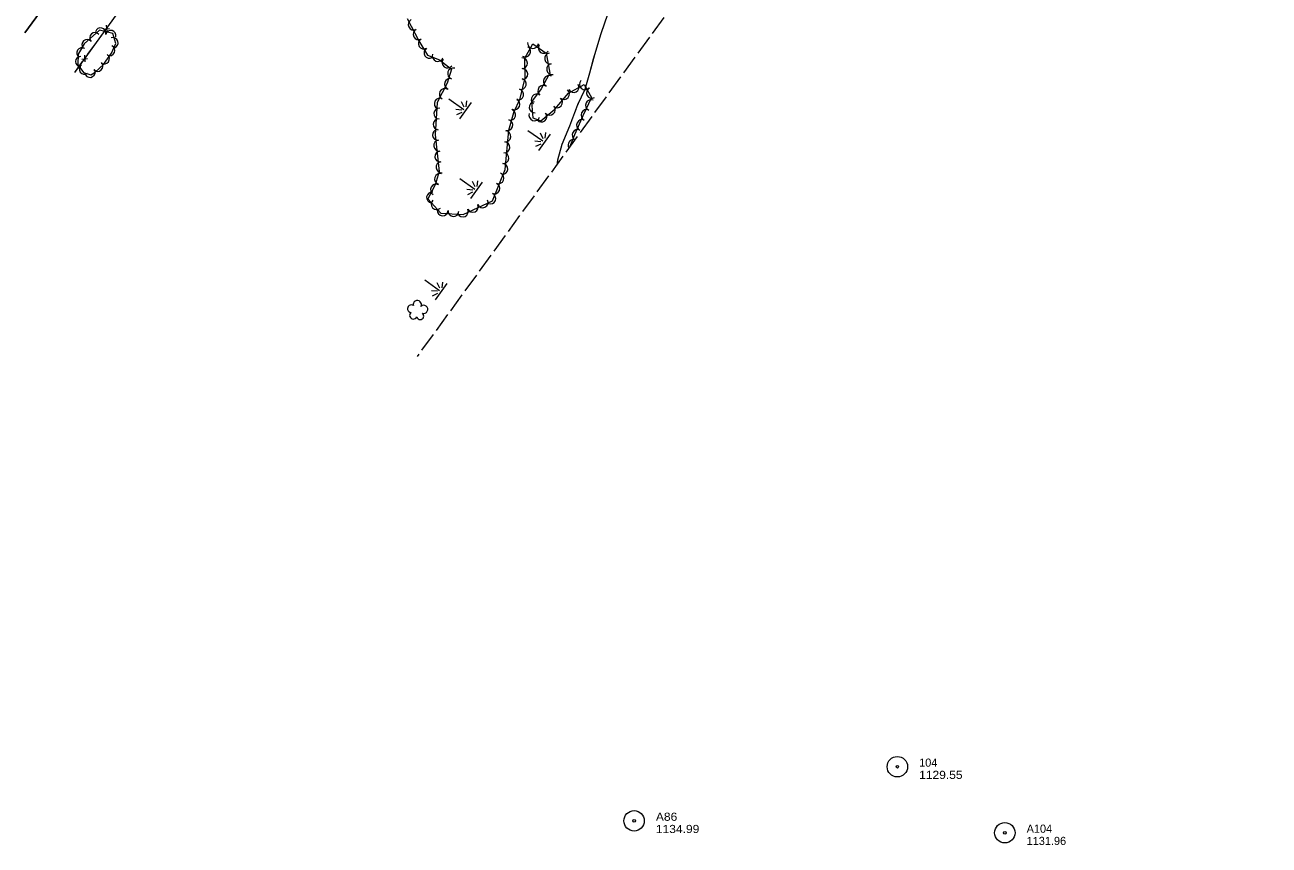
# Model space of a CAD drawing. Extents: x 297327 to 299792, y 46897 to 49095.
# Drawn here: x 298407 to 299321, y 46897 to 47500 of the extents above; entities that cross this region are included whole.
import ezdxf

# ---------------------------------------------------------------- set-up
doc = ezdxf.new("R2010")
doc.units = 0
doc.header["$LTSCALE"] = 2.4
doc.linetypes.add('LONG_DASHED', pattern=[7.5, 6, -1.5])
for name, color, linetype, lineweight in [('11', 7, 'Continuous', 25), ('15', 7, 'Continuous', 13), ('18', 7, 'Continuous', 13), ('19', 7, 'Continuous', 13), ('4', 7, 'Continuous', 13), ('6', 7, 'Continuous', 13)]:
    doc.layers.add(name, color=color, linetype=linetype, lineweight=lineweight)

msp = doc.modelspace()

# ---------------------------------------------------------------- linework, layer by layer
at = {"layer": '11'}
msp.add_lwpolyline([(298407.334, 47494.128), (298425.338, 47519.051)], dxfattribs=at)
at = {"layer": '15'}
for p, q in [((298467.752, 47494.906), (298467.331, 47499.713)), ((298459.972, 47487.112), (298465.708, 47494.99)), ((298465.288, 47496.907), (298469.407, 47497.292)), ((298453.451, 47478.155), (298459.972, 47487.112)), ((298443.923, 47465.07), (298449.659, 47472.948)), ((298449.238, 47474.864), (298453.358, 47475.25)), ((298451.703, 47472.864), (298451.282, 47477.671))]:
    msp.add_line(p, q, dxfattribs=at)
msp.add_lwpolyline([(298443.923, 47465.07), (298477.895, 47511.728), (298522.34, 47573.628), (298562.948, 47631.443), (298626.887, 47719.694), (298679.84, 47793.758), (298726.071, 47859.836), (298761.348, 47908.474)], dxfattribs=at)
at = {"layer": '18'}
for points in [[(298688.247, 47504.735), (298696.782, 47488.144), (298703.052, 47477.653), (298711.875, 47474.359), (298720.699, 47467.348), (298717.507, 47457.047), (298710.255, 47442.95), (298708.668, 47419.095), (298711.63, 47392.114), (298708.74, 47382.356), (298703.299, 47372.237), (298712.927, 47361.712), (298729.23, 47360.666), (298750.752, 47370.587), (298760.106, 47393.656), (298762.882, 47422.635), (298766.496, 47435.556), (298771.16, 47445.873), (298774.908, 47461.049), (298774.503, 47475.598), (298780.567, 47486.027), (298790.234, 47479.244), (298792.994, 47464.419), (298786.661, 47453.01), (298779.394, 47443.515), (298780.376, 47431.746), (298786.338, 47429.568), (298796.702, 47437.942), (298806.656, 47449.891), (298818.241, 47456.243), (298823.43, 47446.552), (298817.29, 47433.055)], [(298817.29, 47433.055), (298811.185, 47419.233), (298807.731, 47410.65)]]:
    msp.add_lwpolyline(points, dxfattribs=at)
msp.add_lwpolyline([(298465.043, 47470.761), (298470.86, 47479.099), (298474.225, 47486.323), (298471.894, 47493.739), (298462.226, 47496.177), (298450.977, 47486.121), (298446.39, 47478.389), (298446.333, 47470.596), (298450.458, 47464.98), (298455.86, 47463.292), (298458.863, 47465.109)], close=True, dxfattribs=at)
for centre, radius, start, end in [((298692.918, 47500.236), 4.004, 117.23056, 297.21524), ((298458.79, 47490.406), 3.845, 41.80266, 221.78734), ((298462.976, 47493.913), 3.845, 345.85435, 165.83902), ((298470.431, 47492.033), 3.845, 345.85435, 165.83902), ((298471.98, 47486.756), 3.845, 287.45666, 107.44134), ((298696.581, 47493.115), 4.004, 117.23056, 297.21524), ((298449.291, 47479.334), 3.845, 59.32918, 239.31385), ((298453.057, 47485.282), 3.845, 41.80266, 221.78734), ((298469.613, 47481.188), 3.845, 245.03116, 65.01584), ((298700.374, 47486.219), 4.004, 120.87253, 300.85721), ((298704.482, 47479.346), 4.004, 120.87253, 300.85721), ((298774.837, 47480.341), 4.004, 239.83156, 59.81624), ((298780.573, 47486.678), 4.004, 174.95165, 354.93633), ((298788.499, 47483.022), 4.004, 144.95165, 324.93633), ((298448.363, 47472.979), 3.845, 89.58859, 269.57327), ((298460.848, 47469.652), 3.845, 222.45255, 42.43723), ((298465.593, 47475.066), 3.845, 235.10613, 55.09081), ((298710.612, 47477.067), 4.004, 159.53492, 339.5196), ((298717.78, 47472.344), 4.004, 141.5392, 321.52387), ((298772.512, 47471.802), 4.004, 271.60219, 91.58687), ((298793.103, 47475.285), 4.004, 100.55379, 280.53847), ((298451.087, 47467.523), 3.845, 126.30526, 306.28994), ((298455.12, 47465.196), 3.845, 211.18418, 31.16886), ((298721.927, 47464.231), 4.004, 72.79087, 252.77555), ((298772.735, 47463.798), 4.004, 271.60219, 91.58687), ((298792.229, 47458.723), 4.004, 60.97353, 240.95821), ((298794.568, 47467.413), 4.004, 100.55379, 280.53847), ((298719.557, 47456.583), 4.004, 72.79087, 252.77555), ((298771.627, 47456.504), 4.004, 256.13499, 76.11967), ((298788.137, 47451.49), 4.004, 52.57902, 232.5637), ((298810.364, 47454.314), 4.004, 208.74341, 28.72809), ((298818.721, 47456.338), 4.004, 138.17427, 318.15895), ((298823.95, 47450.021), 4.004, 118.17427, 298.15895), ((298712.119, 47441.993), 4.004, 62.78476, 242.76943), ((298715.782, 47449.113), 4.004, 62.78476, 242.76943), ((298766.951, 47441.651), 4.004, 245.68139, 65.66607), ((298769.707, 47448.731), 4.004, 256.13499, 76.11967), ((298783.27, 47445.131), 4.004, 52.57902, 232.5637), ((298798.238, 47443.06), 4.004, 230.212, 50.19668), ((298803.363, 47449.212), 4.004, 230.212, 50.19668), ((298823.187, 47440.956), 4.004, 65.54612, 245.5308), ((298711.815, 47434.823), 4.004, 86.20156, 266.18624), ((298763.867, 47433.938), 4.004, 254.38137, 74.36605), ((298781.846, 47439.337), 4.004, 94.77735, 274.76202), ((298792.98, 47437.629), 4.004, 218.9455, 38.93017), ((298819.871, 47433.667), 4.004, 65.54612, 245.5308), ((298711.283, 47426.833), 4.004, 86.20156, 266.18624), ((298761.71, 47426.227), 4.004, 254.38137, 74.36605), ((298781.626, 47433.521), 4.004, 159.93972, 339.9244), ((298786.752, 47432.596), 4.004, 218.9455, 38.93017), ((298816.629, 47426.371), 4.004, 66.17723, 246.16191), ((298710.763, 47419.212), 4.004, 96.27256, 276.25724), ((298760.332, 47417.993), 4.004, 264.53579, 84.52047), ((298813.394, 47419.047), 4.004, 66.17723, 239.12331), ((298711.637, 47411.253), 4.004, 96.27256, 276.25724), ((298759.569, 47410.022), 4.004, 264.53579, 84.52047), ((298810.41, 47411.692), 4.004, 76.79338, 211.14885), ((298712.511, 47403.293), 4.004, 96.27256, 276.25724), ((298713.385, 47395.334), 4.004, 96.27256, 276.25724), ((298758.805, 47402.052), 4.004, 264.53579, 84.52047), ((298712.22, 47386.726), 4.004, 73.5101, 253.49478), ((298755.24, 47387.233), 4.004, 247.93613, 67.92081), ((298758.041, 47394.081), 4.004, 264.53579, 84.52047), ((298709.246, 47378.872), 4.004, 61.74068, 241.72536), ((298752.231, 47379.812), 4.004, 247.93613, 67.92081), ((298706.428, 47373.096), 4.004, 81.74068, 261.72536), ((298709.809, 47368.225), 4.004, 132.45914, 312.44381), ((298743.6, 47369.598), 4.004, 204.75595, 24.74063), ((298749.222, 47372.392), 4.004, 247.93613, 67.92081), ((298714.156, 47363.733), 4.004, 176.3366, 356.32128), ((298722.146, 47363.22), 4.004, 176.3366, 356.32128), ((298729.056, 47362.893), 4.004, 204.75595, 24.74063), ((298736.328, 47366.246), 4.004, 204.75595, 24.74063), ((298691.185, 47291.385), 2.777, 55.80256, 263.57555), ((298695.631, 47294.404), 2.974, 332.83167, 194.06555), ((298700.326, 47290.908), 2.975, 250.48248, 133.45575), ((298692.754, 47286.573), 2.783, 132.47957, 333.49062), ((298697.765, 47286.015), 2.611, 195.18772, 53.12032)]:
    msp.add_arc(centre, radius, start, end, dxfattribs=at)
at = {"layer": '19'}
for p, q in [((298718.841, 47445.699), (298729.754, 47437.889)), ((298728.327, 47437.219), (298723.916, 47437.671)), ((298724.603, 47434), (298728.447, 47435.78)), ((298726.774, 47430.891), (298735.385, 47442.922)), ((298729.96, 47439.5), (298728.109, 47443.53)), ((298731.805, 47444.063), (298731.36, 47439.85)), ((298812.034, 47437.748), (298811.319, 47435.864)), ((298814.351, 47443.324), (298813.49, 47441.504)), ((298809.889, 47432.097), (298809.174, 47430.213)), ((298776.858, 47422.46), (298787.771, 47414.65)), ((298784.791, 47407.652), (298793.402, 47419.683)), ((298787.977, 47416.261), (298786.126, 47420.291)), ((298789.822, 47420.824), (298789.377, 47416.611)), ((298786.344, 47413.98), (298781.933, 47414.432)), ((298782.62, 47410.761), (298786.464, 47412.541)), ((298798.384, 47398.895), (298798.326, 47397.718)), ((298726.886, 47387.078), (298737.799, 47379.268)), ((298734.819, 47372.27), (298743.43, 47384.301)), ((298738.005, 47380.879), (298736.154, 47384.909)), ((298739.85, 47385.442), (298739.405, 47381.229)), ((298736.372, 47378.598), (298731.961, 47379.05)), ((298732.648, 47375.379), (298736.492, 47377.159)), ((298701.029, 47312.649), (298711.942, 47304.839)), ((298708.962, 47297.841), (298717.573, 47309.872)), ((298712.148, 47306.45), (298710.297, 47310.48)), ((298713.993, 47311.013), (298713.548, 47306.8)), ((298710.515, 47304.169), (298706.104, 47304.621)), ((298706.791, 47300.95), (298710.635, 47302.73))]:
    msp.add_line(p, q, dxfattribs=at)
for points in [[(298856.47, 47622.438), (298862.814, 47608.969), (298866.377, 47596.465), (298867.095, 47584.937), (298863.901, 47567.991), (298863.47, 47548.37), (298859.834, 47537.481), (298849.775, 47526.923), (298840.874, 47517.564), (298835.411, 47507.537), (298830.295, 47493.442), (298825.658, 47477.877), (298822.145, 47464.56), (298818.645, 47452.401), (298813.336, 47441.178), (298807.387, 47425.507), (298801.758, 47412.038), (298798.463, 47400.49), (298798.326, 47397.719)], [(298833.619, 47502.601), (298830.295, 47493.442), (298825.658, 47477.877), (298824.835, 47474.756)], [(298824.835, 47474.756), (298822.145, 47464.56), (298818.645, 47452.401), (298816.074, 47446.965)], [(298807.743, 47426.446), (298807.387, 47425.507), (298801.758, 47412.038), (298798.463, 47400.49), (298798.384, 47398.895)]]:
    msp.add_lwpolyline(points, dxfattribs=at)
at = {"layer": '4', "linetype": 'LONG_DASHED'}
msp.add_line((299321.306, 48116.776), (298695.48, 47256.313), dxfattribs=at)
at = {"layer": '6'}
for centre, radius in [((299048.222, 46954.867), 7.5), ((299048.222, 46954.867), 0.96), ((298854.847, 46915.11), 7.5), ((298854.847, 46915.11), 0.96), ((299127.19, 46906.33), 7.5), ((299127.19, 46906.33), 0.96)]:
    msp.add_circle(centre, radius, dxfattribs=at)

# ---------------------------------------------------------------- texts
for s, p in [('104', (299064.222, 46954.867)), ('A104', (299143.19, 46906.33)), ('1131.96', (299143.19, 46897.33))]:
    msp.add_text(s, height=6, dxfattribs=at).set_placement(p)
at = {"layer": '6', "width": 1.1}
for s, p in [('1129.55', (299064.222, 46945.867)), ('A86', (298870.847, 46915.11)), ('1134.99', (298870.847, 46906.11))]:
    msp.add_text(s, height=6, dxfattribs=at).set_placement(p)

doc.saveas('drawing.dxf')
